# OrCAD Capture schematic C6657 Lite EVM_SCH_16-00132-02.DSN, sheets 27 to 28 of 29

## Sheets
27 PAGE26 : SMART REF & CORE VOLT: size C; title: UCD9222RGZR
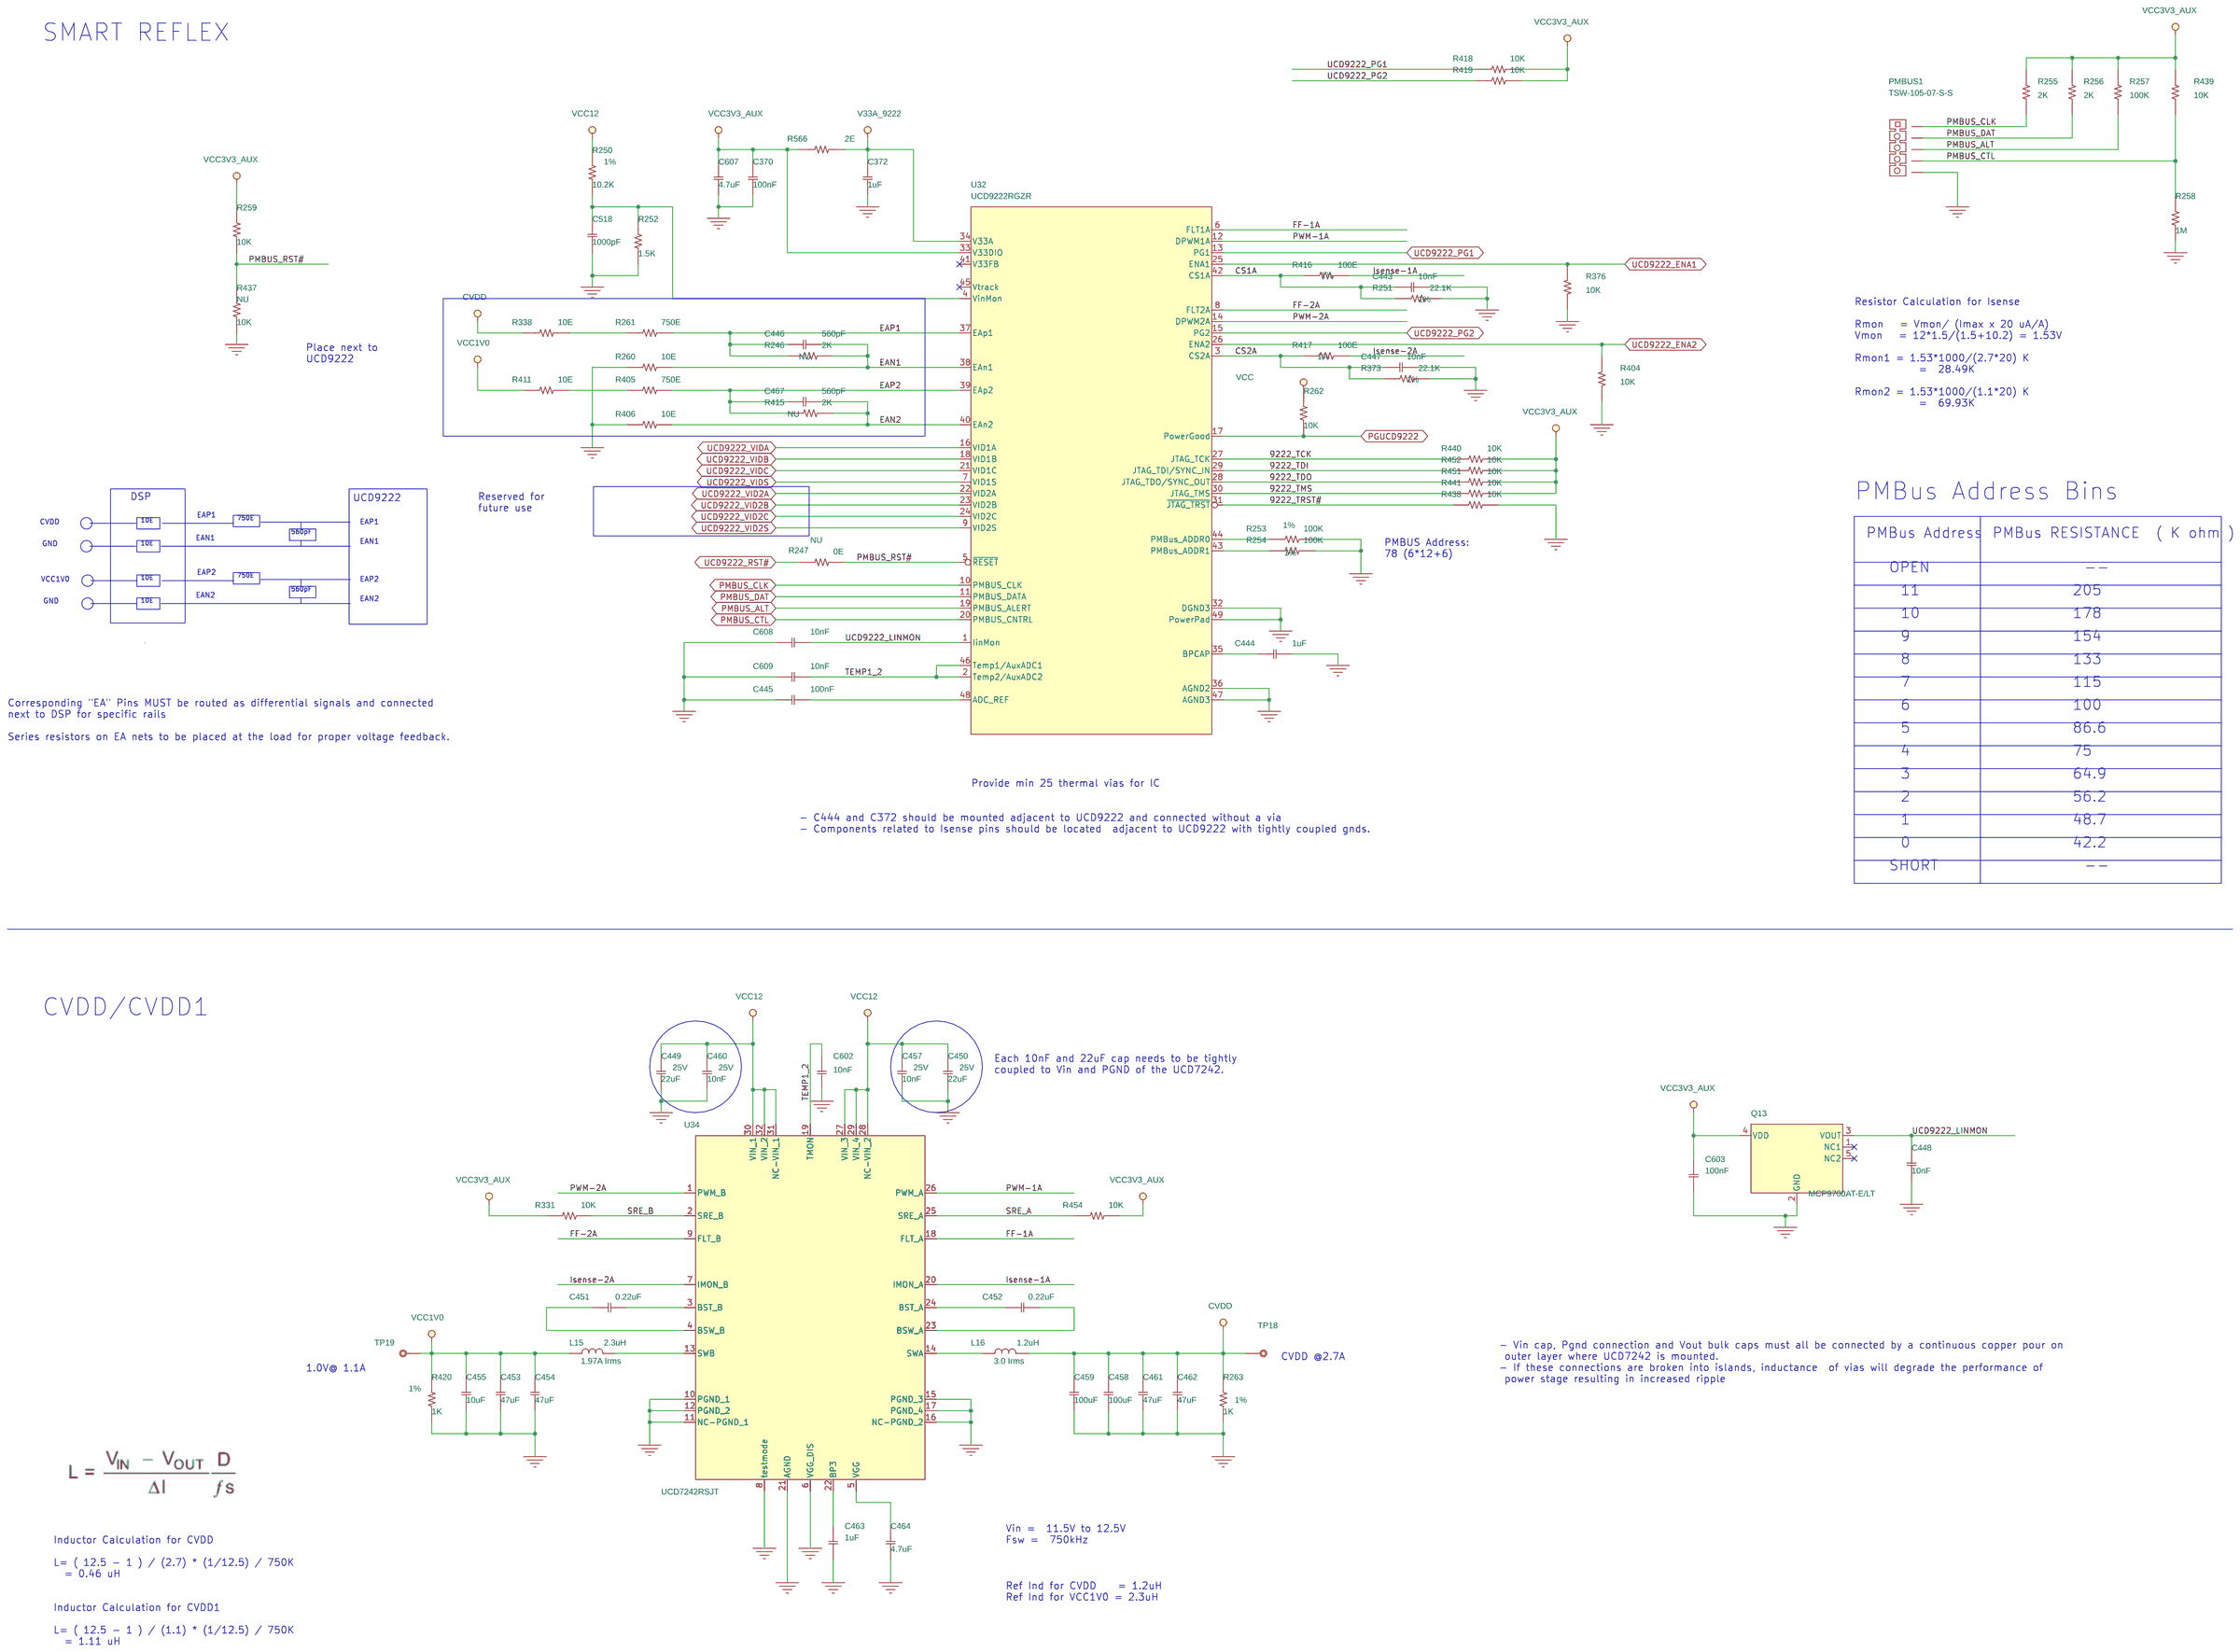
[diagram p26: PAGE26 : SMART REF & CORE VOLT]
28 PAGE18 : DSP-CLOCK & SMART REF: size C; title: DSP-CLOCK & SMART REFLEX
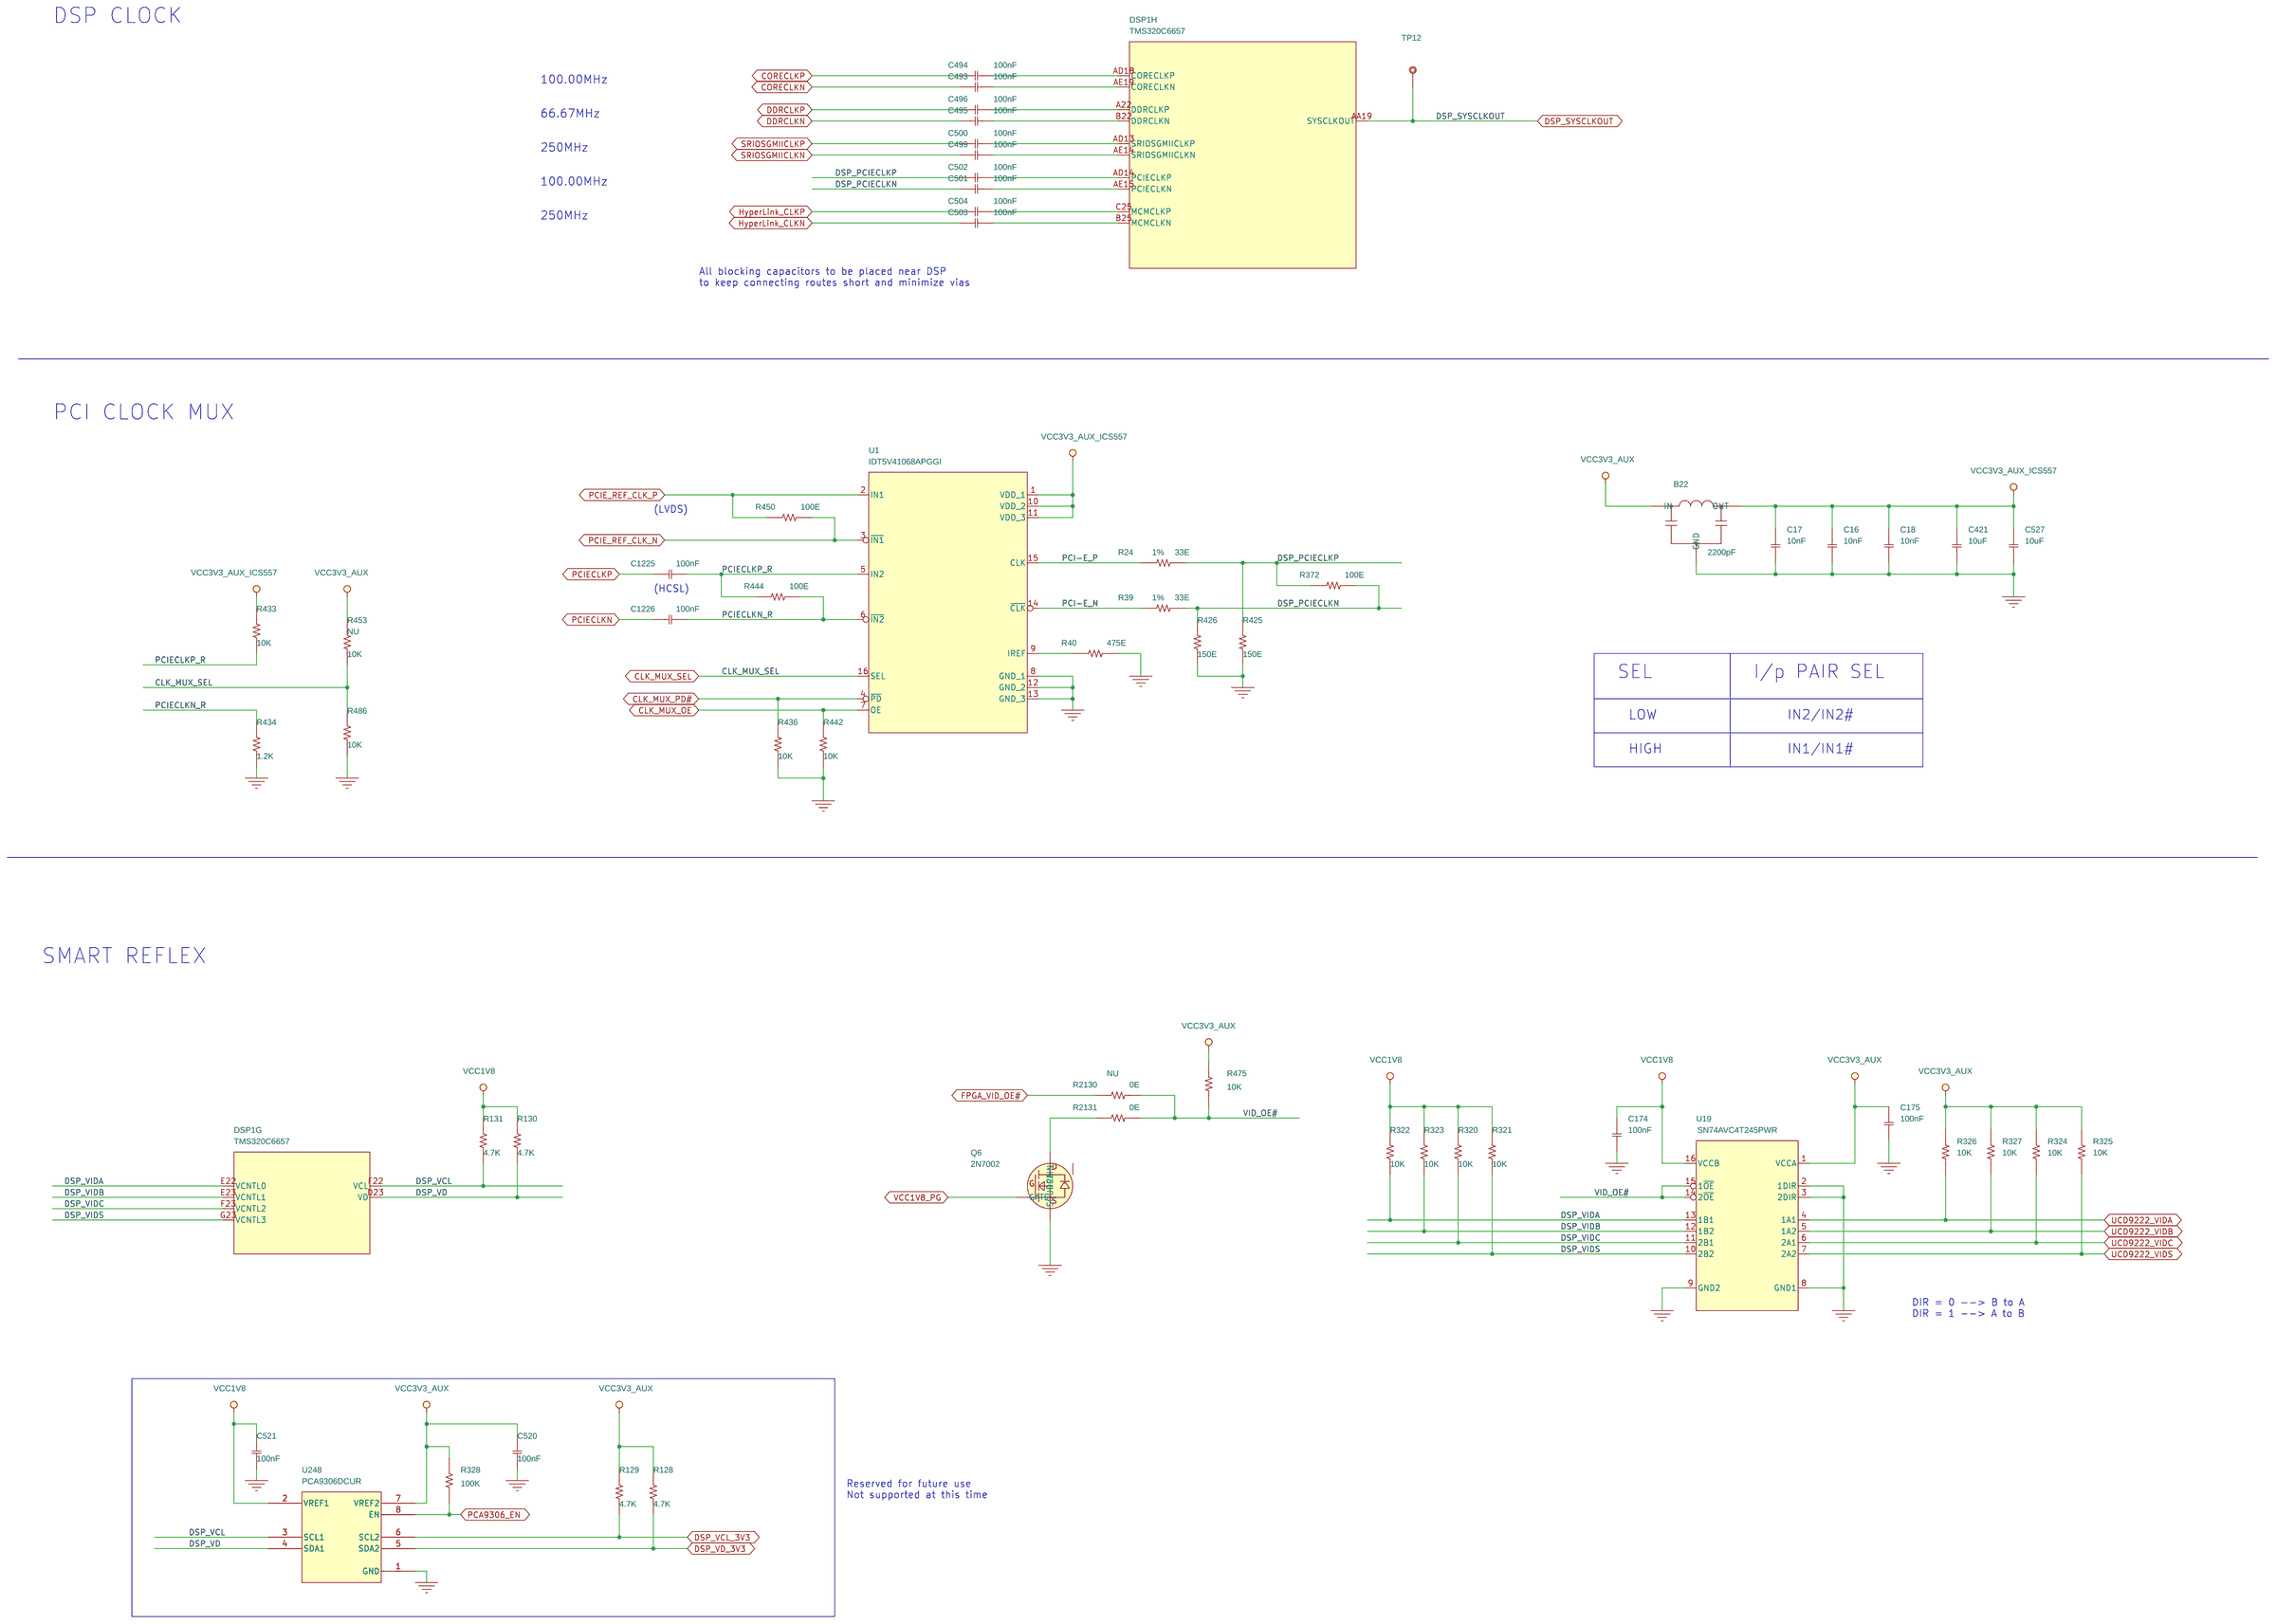
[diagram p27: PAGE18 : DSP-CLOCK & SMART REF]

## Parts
sheet PAGE18 : DSP-CLOCK & SMART REF
B22  2200pF  [L_3P_70_63X35]
C16  10nF  [C0402]
C17  10nF  [C0402]
C18  10nF  [C0402]
C174  100nF  [C0402]
C175  100nF  [C0402]
C421  10uF  [C0603]
C493  100nF  [C0402]
C494  100nF  [C0402]
C495  100nF  [C0402]
C496  100nF  [C0402]
C499  100nF  [C0402]
C500  100nF  [C0402]
C501  100nF  [C0402]
C502  100nF  [C0402]
C503  100nF  [C0402]
C504  100nF  [C0402]
C520  100nF  [C0402]
C521  100nF  [C0402]
C527  10uF  [C0603]
C1225  100nF  [C0402]
C1226  100nF  [C0402]
Q6  2N7002  [SOT-23]
R24  33E  [R0402]
R39  33E  [R0402]
R40  475E  [R0402]
R128  4.7K  [R0402]
R129  4.7K  [R0402]
R130  4.7K  [R0402]
R131  4.7K  [R0402]
R320  10K  [R0402]
R321  10K  [R0402]
R322  10K  [R0402]
R323  10K  [R0402]
R324  10K  [R0402]
R325  10K  [R0402]
R326  10K  [R0402]
R327  10K  [R0402]
R328  100K  [R0402]
R372  100E  [R0402]
R425  150E  [R0402]
R426  150E  [R0402]
R433  10K  [R0402]
R434  1.2K  [R0402]
R436  10K  [R0402]
R442  10K  [R0402]
R444  100E  [R0402]
R450  100E  [R0402]
R453  10K  [R0402]
R475  10K  [R0402]
R486  10K  [R0402]
R2130  0E  [R0402]
R2131  0E  [R0402]
TP12  Test Point  [TP-S40]
U1  IDT5V41068APGGI  [SOIC_16P_26_197x252]
U19  SN74AVC4T245PWR  [SOIC_16P_26_197x252]
U248  PCA9306DCUR  [SOIC_8P_20_79X122]
sheet PAGE25 : DSP_POWER 2
DSP1  TMS320C6657  [BGA80P_38X38_625_SKT_EINF]  (sections A,B,C,D,E,F,G,H,I,J,K,L,M,N,O,P,Q,R,S,T)
sheet PAGE26 : SMART REF & CORE VOLT
C370  100nF  [C0402]
C372  1uF  [C0402]
C443  10nF  [C0402]
C444  1uF  [C0402]
C445  100nF  [C0402]
C446  560pF  [C0402]
C447  10nF  [C0402]
C448  10nF  [C0402]
C449  22uF  [C1206-1]
C450  22uF  [C1206-1]
C451  0.22uF  [C0603]
C452  0.22uF  [C0603]
C453  47uF  [C0805]
C454  47uF  [C0805]
C455  10uF  [C0603]
C457  10nF  [C0402]
C458  100uF  [C1206-1]
C459  100uF  [C1206-1]
C460  10nF  [C0402]
C461  47uF  [C0805]
C462  47uF  [C0805]
C463  1uF  [C0402]
C464  4.7uF  [C0603]
C467  560pF  [C0402]
C518  1000pF  [C0402]
C602  10nF  [C0402]
C603  100nF  [C0402]
C607  4.7uF  [C0603]
C608  10nF  [C0402]
C609  10nF  [C0402]
L15  2.3uH  [IND_NRG4026]
L16  1.2uH  [CHK_ELL-5PRR47N]
PMBUS1  TSW-105-07-S-S  [HD_5x1P_100_D]
Q13  MCP9700AT-E/LT  [SC-70_5P]
R246  2K  [R0402]
R247  0E  [R0402]
R250  10.2K  [R0603]
R251  22.1K  [R0603]
R252  1.5K  [R0603]
R253  100K  [R0402]
R254  100K  [R0402]
R255  2K  [R0402]
R256  2K  [R0402]
R257  100K  [R0402]
R258  1M  [R0402]
R259  10K  [R0402]
R260  10E  [R0402]
R261  750E  [R0402]
R262  10K  [R0402]
R263  1K  [R0402]
R331  10K  [R0402]
R338  10E  [R0402]
R373  22.1K  [R0603]
R376  10K  [R0402]
R404  10K  [R0402]
R405  750E  [R0402]
R406  10E  [R0402]
R411  10E  [R0402]
R415  2K  [R0402]
R416  100E  [R0402]
R417  100E  [R0402]
R418  10K  [R0402]
R419  10K  [R0402]
R420  1K  [R0402]
R437  10K  [R0402]
R438  10K  [R0402]
R439  10K  [R0402]
R440  10K  [R0402]
R441  10K  [R0402]
R451  10K  [R0402]
R452  10K  [R0402]
R454  10K  [R0402]
R566  2E  [R0402]
TP18  Test Point  [TP-S40]
TP19  Test Point  [TP-S40]
U32  UCD9222RGZR  [QFN_48P_20_276x276_TP202V25]
U34  UCD7242RSJT  [QFN_32P_20_236x236_UDC7242]

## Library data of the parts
B22 = 1212_FILTER_NFW31SP106X1E4L_0: FILTER LC HIGH FREQ 2200PF 0603; Manufacture Part Number: NFM18CC222R1C3D; Mfg: Murata; Mfg Part#: NFM18CC222R1C3D; Oper. Temp. Range: -55C to 125C; Package: 0603; ProcessType: SMT; RoHS: Yes; Tolerance: 20%; Vendor: DigiKey; Vendor Part#: NFM18CC222R1C3D-ND; eI Part#: 04_00026_01
C16-C18 C443 C447 C448 C602 C608 C609 = 11_C_0: CAP 10nF 16V CERAMIC 0402 SMD; Alt Mfg: Murata; Alt Mfg Part#: GRM155R71C103KA01D; Manufacture Part Number: C1005X7R1C103K||2238 787 15636||CC0402KRX7R7BB103; Mfg: Panasonic - ECG; Mfg Part#: ECJ-0EB1C103K; Oper. Temp. Range: -55C to 125C; Package: 0402; ProcessType: SMT; RoHS: Yes; Tolerance: 10%; Vendor: DigiKey; Vendor Part#: PCC103BQCT-ND; eI Part#: 03_00025_01
C174 C175 C370 C445 C495 C496 C499-C504 C520 C521 C603 C1225 C1226 = 11_C_0: CAP CER 0.1UF 10V 10% X5R 0402; Alt Mfg: Murata; Alt Mfg Part#: GRM155R61A104KA01D; Manufacture Part Number: 2238 787 15649||CC0402KRX7R7BB104; Mfg: Yageo; Mfg Part#: CC0402KRX5R6BB104; Oper. Temp. Range: -55C to 85C; Package: 0402; ProcessType: SMT; RoHS: Yes; Tolerance: 10%; Vendor: DigiKey; Vendor Part#: 311-1336-1-ND; eI Part#: 03_00021_02
C421 C455 C527 = 11_C_0: CAP CER 10UF 6.3V 20% X5R 0603; Manufacture Part Number: C1608X5R0J106MT||2255 206 13776||CC0603MRX5R5BB106; Mfg: Murata; Mfg Part#: GRM188R60J106ME47D; Oper. Temp. Range: -55C to 85C; Package: 0603; ProcessType: SMT; RoHS: Yes; Tolerance: 20%; Vendor: DigiKey; Vendor Part#: 490-3896-1-ND; eI Part#: 03_00058_03
C493 C494 = 11_C_0: CAP CER 0.1UF 10V 10% X5R 0402; Alt Mfg: Murata; Alt Mfg Part#: GRM155R61A104KA01D; Manufacture Part Number: CC0402KRX7R7BB104; Mfg: Yageo; Mfg Part#: CC0402KRX5R6BB104; Oper. Temp. Range: -55C to 85C; Package: 0402; ProcessType: SMT; RoHS: Yes; Tolerance: 10%; Vendor: DigiKey; Vendor Part#: 311-1336-1-ND; eI Part#: 03_00021_02
Q6 = 131_N_MOS_SOT-23_1: MOSFET N-CH 60V 300MA SOT-23; Mfg: NXP Semiconductors; Mfg Part#: 2N7002,215; ProcessType: SMT; RoHS: Yes; Vendor: DigiKey; Vendor Part#: 568-1369-2-ND; eI Part#: 07_00015_02
R24 R39 = 10_R_0: RES 33.0 OHM 1/10W 1% 0402 SMD; Alt Mfg: Yageo; Alt Mfg Part#: RC0402FR-0733RL; Manufacture Part Number: 0402WGJ0330TCE||232270570339L||RC0402JR-0733RL||RM04JTN330; Mfg: Panasonic - ECG; Mfg Part#: ERJ-2RKF33R0X; Oper. Temp. Range: -55C to 125C; Package: 0402; ProcessType: SMT; Remark: Alt part is 1/16W; RoHS: Yes; Tolerance: 1%; Vendor: DigiKey; Vendor Part#: P33.0LCT-ND; eI Part#: 02_00018_05
R40 = 10_R_0: RES 475 OHM 1/10W 1% 0402 SMD; Manufacture Part Number: 0402WGF4750T5E||RM04FTN4750; Mfg: Panasonic - ECG; Mfg Part#: ERJ-2RKF4750X; Oper. Temp. Range: -55C to 125C; Package: 0402; ProcessType: SMT; Remark: Alt part is 1/16W; RoHS: Yes; Tolerance: 1%; Vendor: DigiKey; Vendor Part#: P475LCT-ND; eI Part#: 02_00690_01
R128-R131 = 10_R_0: RES 4.7K OHM 1/10W 5% 0402 SMD; Alt Mfg: Yageo; Alt Mfg Part#: RC0402JR-074K7L; Manufacture Part Number: 0402WGJ0472TCE||RC0402JR-074K7L||RM04JTN472; Mfg: Panasonic - ECG; Mfg Part#: ERJ-2GEJ472X; Oper. Temp. Range: -55C to 125C; Package: 0402; ProcessType: SMT; Remark: Alt part is 1/16W; RoHS: Yes; Tolerance: 5%; Vendor: DigiKey; Vendor Part#: P4.7KJCT-ND; eI Part#: 02_00023_01
R259 R262 R320-R327 R331 R376 R404 R418 R419 R436 R438-R442 R451 R452 R454 R475 R486 = 10_R_0: RES 10.0K OHM 1/10W 1% 0402 SMD; Alt Mfg: Yageo; Alt Mfg Part#: RC0402FR-0710KL; Manufacture Part Number: 0402WGF1002TCE||RM04FTN1002; Mfg: Panasonic - ECG; Mfg Part#: ERJ-2RKF1002X; Oper. Temp. Range: -55C ~ 125C; Package: 0402; ProcessType: SMT; Remark: Alt part is 1/16W; RoHS: Yes; Tolerance: 1%; Vendor: DigiKey; Vendor Part#: P10.0KLCT-ND; eI Part#: 02_00027_01
R328 = 10_R_0: RES 100K OHM 1/10W 1% 0402 SMD; Alt Mfg: Yageo; Alt Mfg Part#: RC0402FR-07100KL; Mfg: Panasonic - ECG; Mfg Part#: ERJ-2RKF1003X; Oper. Temp. Range: ±100ppm/°C; Package: 0402; ProcessType: SMT; RoHS: Yes; Tolerance: 1%; Vendor: DigiKey; Vendor Part#: P100KLCT-ND; eI Part#: 02_00262_01
R372 R444 R450 = 10_R_0: RES 100 OHM 1/10W 1% 0402 SMD; Manufacture Part Number: 0402WGJ0101TCE||RM04JTN101; Mfg: Panasonic - ECG; Mfg Part#: ERJ-2RKF1000X; Oper. Temp. Range: -55C to 125C; Package: 0402; ProcessType: SMT; RoHS: Yes; Tolerance: 1%; Vendor: DigiKey; Vendor Part#: P100LCT-ND; eI Part#: 02_00043_02
R425 R426 = 10_R_0: RES 150 OHM 1/10W 1% 0402 SMD; Manufacture Part Number: 0402WGF1500TCE||RM04FTN1500; Mfg: Panasonic - ECG; Mfg Part#: ERJ-2RKF1500X; Oper. Temp. Range: -55C to 125C; Package: 0402; ProcessType: SMT; RoHS: Yes; Tolerance: 1%; Vendor: DigiKey; Vendor Part#: P150LCT-ND; eI Part#: 02_00449_01
R433 = 10_R_0: RES 10.0K OHM 1/10W 1% 0402 SMD; Alt Mfg: Yageo; Alt Mfg Part#: RC0402FR-0710KL; Manufacture Part Number: 0402WGF1002TCE||RM04FTN1002; Mfg: Panasonic - ECG; Mfg Part#: ERJ-2RKF1002X; Oper. Temp. Range: -55C to 125C; Package: 0402; ProcessType: SMT; Remark: Alt part is 1/16W; RoHS: Yes; Tolerance: 1%; Vendor: DigiKey; Vendor Part#: P10.0KLCT-ND; eI Part#: 02_00027_01
R434 = 10_R_0: RES 1.20K OHM 1/10W 1% 0402 SMD; Alt Mfg: Yageo; Alt Mfg Part#: RC0402FR-071K2L; Mfg: Panasonic - ECG; Mfg Part#: ERJ-2RKF1201X; Oper. Temp. Range: -55C to 125C; Package: 0402; ProcessType: SMT; RoHS: Yes; Tolerance: 1%; Vendor: DigiKey; Vendor Part#: P1.20KLCT-ND; eI Part#: 02_00143_03
R437 R453 = 10_R_0: RES 10.0K OHM 1/10W 1% 0402 SMD; Alt Mfg: Yageo; Alt Mfg Part#: RC0402FR-0710KL; Manufacture Part Number: 0402WGF1002TCE||RM04FTN1002; Mfg: Panasonic - ECG; Mfg Part#: ERJ-2RKF1002X; Mounting Status: NU; Mounting_Status: NU; Oper. Temp. Range: -55C ~ 125C; Package: 0402; ProcessType: SMT; Remark: Alt part is 1/16W; RoHS: Yes; Tolerance: 1%; Vendor: DigiKey; Vendor Part#: P10.0KLCT-ND; eI Part#: 02_00027_01
R247 R2130 = 10_R_0: RES ZERO OHM 1/10W 5% 0402 SMD; Alt Mfg: Yageo; Alt Mfg Part#: RC0402JR-070RL; Mfg: Panasonic - ECG; Mfg Part#: ERJ-2GE0R00X; Mounting Status: NU; Mounting_Status: NU; Oper. Temp. Range: -55C to 125C; Package: 0402; ProcessType: SMT; Remark: Alt part is 1/16W; RoHS: Yes; Tolerance: 5%; Vendor: DigiKey; Vendor Part#: P0.0JCT-ND; eI Part#: 02_00019_01
R2131 = 10_R_0: RES ZERO OHM 1/10W 5% 0402 SMD; Alt Mfg: Yageo; Alt Mfg Part#: RC0402JR-070RL; Mfg: Panasonic - ECG; Mfg Part#: ERJ-2GE0R00X; Oper. Temp. Range: -55C to 125C; Package: 0402; ProcessType: SMT; Remark: Alt part is 1/16W; RoHS: Yes; Tolerance: 5%; Vendor: DigiKey; Vendor Part#: P0.0JCT-ND; eI Part#: 02_00019_01
TP12 TP18 TP19 = 00_TP-S40_0: TEST PAD TP-S40; Mfg: --NA--; Mfg Part#: --NA--; Oper. Temp. Range: --NA--; Package: --NA--; ProcessType: SMT; RoHS: Yes; Vendor: --NA--; Vendor Part#: --NA--; eI Part#: --NA--
U1 = ICS557GI-08LFT_0: IC CLK MUX 2:1 16TSSOP; Mfg: IDT, Integrated Device Technology Inc; Oper. Temp. Range: -40°C ~ 85°C; Package: 16-TSSOP; RoHS: Yes; Specifications: IC CLK MUX 2:1 16TSSOP; Vendor: DigiKey; Vendor Part#: 800-2530-5-ND; eI Part#: 01_00854_01
U19 = SN74AVC4T245PWR: IC BUS TRANSCVR 4BIT 16TSSOP; Mfg: Texas Instruments; Oper. Temp. Range: -40°C ~ 85°C; Package: 16-TSSOP; RoHS: Yes; Specifications: IC BUS TRANSCVR 4BIT 16TSSOP; Vendor: Texas Instruments; eI Part#: 01_00045_01
U248 = PCA9306: IC, Dual I2C Voltage Translator; Alt Mfg: NXP Semiconductors; Alt Mfg Part#: PCA9306DC1,125; Mfg: Texas Instruments; Oper. Temp. Range: -40C to 85C; Package: 8-VSSOP; RoHS: Yes; Specifications: IC, Dual I2C Voltage Translator; Vendor: Digikey; Vendor Part#: 296-17988-1-ND; eI Part#: 01_00044_01
DSP1 = TMS320C6657: TI DSP, Dual C66x™ DSP Cores; Mfg: Texas Instruments; RoHS: Yes; Vendor: Texas Instruments; eI Part#: 01_00878_01
C372 C444 C463 = 11_C_0: CAP CER 1.0UF 16V X5R 0402; Manufacture Part Number: C1005X5R0J105KT||C0402B105K007T; Mfg: TDK Corp; Mfg Part#: C1005X5R1C105K; Oper. Temp. Range: -55C to 85C; Package: 0402; ProcessType: SMT; RoHS: Yes; Tolerance: 10%; Vendor: DigiKey; Vendor Part#: 445-4978-1-ND; eI Part#: 03_00264_01
C446 C467 = 11_C_0: CAP CER 560PF 50V 10% X7R 0402; Alt Mfg: AVX; Alt Mfg Part#: 04025C561KAT2A; Manufacture Part Number: 223858715619; Mfg: Yageo; Mfg Part#: CC0402KRX7R9BB561; Oper. Temp. Range: -55C to 125C; Package: 0402; ProcessType: SMT; RoHS: Yes; Tolerance: 10%; Vendor: DigiKey; Vendor Part#: 311-1029-1-ND; eI Part#: 03_00108_05
C449 C450 = 11_C_0: CAP CER 22UF 25V 10% X5R 1206; Manufacture Part Number: KC30R1C226M-T; Mfg: Murata; Mfg Part#: GRM31CR61E226KE15L; Oper. Temp. Range: -55C to 85C; Package: 1206; ProcessType: SMT; RoHS: Yes; Tolerance: 10%; Vendor: DigiKey; Vendor Part#: 490-5527-1-ND; Voltage: 25V; eI Part#: 03_00442_01
C451 C452 = 11_C_0: CAP CER 0.22UF 25V 10% X7R 0603; Manufacture Part Number: C0603X224K025T; Mfg: Murata; Mfg Part#: GRM188R71E224KA88D; Oper. Temp. Range: -55C ~ 125C; Package: 0603; ProcessType: SMT; RoHS: Yes; Tolerance: 10%; Vendor: DigiKey; Vendor Part#: 490-3290-1-ND; eI Part#: 03_00115_01
C453 C454 C461 C462 = 11_C_0: CAP CER 47UF 6.3V 20% X5R 0805; Mfg: Taiyo Yuden; Mfg Part#: JMK212BJ476MG-T; Oper. Temp. Range: -55C to 105C; Package: 0805; ProcessType: SMT; RoHS: Yes; Tolerance: 20%; Vendor: DigiKey; Vendor Part#: 587-1779-1-ND; eI Part#: 03_00328_01
C457 C460 = 11_C_0: CAP CER 10000PF 25V 10% X7R 0402; Mfg: Yageo; Mfg Part#: CC0402KRX7R8BB103; Oper. Temp. Range: -55C to 125C; Package: 0402; ProcessType: SMT; RoHS: Yes; Tolerance: 10%; Vendor: DigiKey; Vendor Part#: 311-1337-1-ND; Voltage: 25V; eI Part#: 03_00029_07
C458 C459 = 11_C_0: CAP CER 100UF 6.3V 20% X5R 1206; Manufacture Part Number: JMK316BJ107ML-T; Mfg: Taiyo Yuden; Mfg Part#: JMK316BJ107ML-T; Oper. Temp. Range: -55C to 85C; Package: 1206; ProcessType: SMT; RoHS: Yes; Tolerance: 20%; Vendor: DigiKey; Vendor Part#: 587-1963-1-ND; Voltage: 6.3V; eI Part#: 03_00380_04
C464 C607 = 11_C_0: CAP CER 4.7UF 10V Y5V 0603; Manufacture Part Number: GRM188R60J475K||C1608X5R0J475KT; Mfg: Murata; Mfg Part#: GRM188F51A475ZE20D; Oper. Temp. Range: -55C to 85C; Package: 0603; ProcessType: SMT; RoHS: Yes; Tolerance: 10%; Vendor: DigiKey; Vendor Part#: 490-3302-1-ND; eI Part#: 03_00276_01
C518 = 11_C_0: CAP CER 1000PF 25V X7R 0402; Manufacture Part Number: 223858715623||CC0402KRX7R9BB102; Mfg: Johnson Dielectrics Inc; Mfg Part#: 250R07W102KV4T; Oper. Temp. Range: -55C to 125C; Package: 0402; ProcessType: SMT; RoHS: Yes; Tolerance: 10%; Vendor: DigiKey; Vendor Part#: 709-1131-1-ND; eI Part#: 03_00289_01
L15 = 1211_CHOKE_0: INDUCTOR 2.3UH 1.97A 30% SMD; Current: 1.97A Irms; Mfg: Taiyo Yuden; Mfg Part#: NRG4026T2R3N; Oper. Temp. Range: -55C ~ 125C; Package: 4.00mm x 4.00mm x 2.60mm; ProcessType: SMT; RoHS: Yes; Tolerance: 30%; Vendor: DigiKey; Vendor Part#: 587-2379-1-ND; eI Part#: 04_00282_01
L16 = 1211_CHOKE_0: COIL CHOKE 1.2UH SHIELDED SMD; Current: 3.0 Irms; Mfg: Panasonic - ECG; Mfg Part#: ELL-5PR1R2N; Oper. Temp. Range: -55C ~ 125C; Package: 5.00mm x 5.00mm x 1.85mm; ProcessType: SMT; RoHS: Yes; Tolerance: 30%; Vendor: DigiKey; Vendor Part#: PCD2372CT-ND; eI Part#: 04_00283_01
PMBUS1 = 1653_JH5X1V_0: CONN HEADER 5POS .100" SGL GOLD; Manufacture Part Number: 205-15GS SERIES||1130-000-05S||21N12564-05S10B-01G-6/3; Mfg: Samtec; Package: PH5x1P-2.54; ProcessType: DIP; RoHS: Yes; Vendor: DigiKey; Vendor Part#: SAM1033-05-ND; eI Part#: 09_00658_01
Q13 = 141_MICROCHIP_MCP9700AT-E-LT_0: IC SENSOR THERMAL 2.3V SC70-5; Mfg: Microchip Technology; Oper. Temp. Range: -40°C ~ 125°C; Package: SC70-5; ProcessType: SMT; RoHS: Yes; Vendor: DigiKey; Vendor Part#: MCP9700AT-E/LTCT-ND; eI Part#: 01_00850_01
R246 R415 = 10_R_0: RES 2.00K OHM 1/10W 1% 0402 SMD; Alt Mfg: TE Connectivity; Alt Mfg Part#: 5-1879208-6; Manufacture Part Number: 0402WGF2001TCE||RM04FTN2001; Mfg: Panasonic - ECG; Mfg Part#: ERJ-2RKF2001X; Mounting Status: NU; Mounting_Status: NU; Oper. Temp. Range: -55C to 125C; Package: 0402; ProcessType: SMT; Remark: Alt part is 1/16W; RoHS: Yes; Tolerance: 1%; Vendor: DigiKey; Vendor Part#: P2.00KLCT-ND; eI Part#: 02_00229_02
R250 = 10_R_0: RES 10.2K OHM 1/10W 1% 0603 SMD; Manufacture Part Number: 0603WAF1022T5E||232270461023L||RM06FTN1022; Mfg: Panasonic - ECG; Mfg Part#: ERJ-3EKF1022V; Oper. Temp. Range: -55C to 125C; Package: 0603; ProcessType: SMT; RoHS: Yes; Tolerance: 1%; Vendor: DigiKey; Vendor Part#: P10.2KHCT-ND; eI Part#: 02_00739_01
R251 R373 = 10_R_0: RES 22.1K OHM 1/10W 1% 0603 SMD; Mfg: Yageo; Mfg Part#: RC0603FR-0722K1L; Oper. Temp. Range: -55C to 125C; Package: 0603; ProcessType: SMT; RoHS: Yes; Tolerance: 1%; Vendor: DigiKey; Vendor Part#: 311-22.1KHRCT-ND; eI Part#: 02_00491_02
R252 = 10_R_0: RES 1.50K OHM 1/10W 1% 0603 SMD; Manufacture Part Number: 0603WAF1501T5E||232270461502L||RM06FTN1501; Mfg: Panasonic - ECG; Mfg Part#: ERJ-3EKF1501V; Oper. Temp. Range: -55C to 125C; Package: 0603; ProcessType: SMT; RoHS: Yes; Tolerance: 1%; Vendor: DigiKey; Vendor Part#: P1.50KHCT-ND; eI Part#: 02_00122_02
R253 R254 R257 = 10_R_0: RES 100K OHM 1/10W 1% 0402 SMD; Alt Mfg: Yageo; Alt Mfg Part#: RC0402FR-07100KL; Manufacture Part Number: 0402WGF1003TCE||RM04FTN1003; Mfg: Panasonic - ECG; Mfg Part#: ERJ-2RKF1003X; Oper. Temp. Range: ±100ppm/°C; Package: 0402; ProcessType: SMT; RoHS: Yes; Tolerance: 1%; Vendor: DigiKey; Vendor Part#: P100KLCT-ND; eI Part#: 02_00262_01
R255 R256 = 10_R_0: RES 2.00K OHM 1/10W 1% 0402 SMD; Alt Mfg: TE Connectivity; Alt Mfg Part#: 5-1879208-6; Manufacture Part Number: 0402WGF2001TCE||RM04FTN2001; Mfg: Panasonic - ECG; Mfg Part#: ERJ-2RKF2001X; Oper. Temp. Range: -55C to 125C; Package: 0402; ProcessType: SMT; Remark: Alt part is 1/16W; RoHS: Yes; Tolerance: 1%; Vendor: DigiKey; Vendor Part#: P2.00KLCT-ND; eI Part#: 02_00229_02
R258 = 10_R_0: RES 1.00M OHM 1/16W 1% 0402 SMD; Manufacture Part Number: 0402WGF4991TCE||RM04FTN4991; Mfg: Yageo; Mfg Part#: RC0402FR-071ML; Mounting Status: NU; Mounting_Status: NU; Oper. Temp. Range: -55C to 125C; Package: 0402; ProcessType: SMT; Remark: Alt part is 1/16W; RoHS: Yes; Tolerance: 1%; Vendor: DigiKey; Vendor Part#: 311-1.00MLRCT-ND; eI Part#: 02_00057_02
R260 R338 R406 R411 = 10_R_0: RES 10.0 OHM 1/10W 1% 0402 SMD; Manufacture Part Number: 0402WGJ0100TCE||RC0402JR-0710RL||RM04JTN100; Mfg: Panasonic - ECG; Mfg Part#: ERJ-2RKF10R0X; Oper. Temp. Range: -55C to 125C; Package: 0402; ProcessType: SMT; RoHS: Yes; Tolerance: 1%; Vendor: DigiKey; Vendor Part#: P10.0LCT-ND; eI Part#: 02_00060_01
R261 R405 = 10_R_0: RES 750 OHM 1/10W 1% 0402 SMD; Manufacture Part Number: 0402WGF7500T5E||0402WGF7500TCE||RM04FTN7500; Mfg: Panasonic - ECG; Mfg Part#: ERJ-2RKF7500X; Oper. Temp. Range: -55C to 125C; Package: 0402; ProcessType: SMT; RoHS: Yes; Tolerance: 1%; Vendor: DigiKey; Vendor Part#: P750LCT-ND; eI Part#: 02_00447_01
R263 R420 = 10_R_0: RES 1.00K OHM 1/10W 1% 0402 SMD; Alt Mfg: Yageo; Alt Mfg Part#: RC0402FR-071KL; Manufacture Part Number: 0402WGF1001TCE||RM04FTN1001; Mfg: Panasonic - ECG; Mfg Part#: ERJ-2RKF1001X; Oper. Temp. Range: -55C to 125C; Package: 0402; ProcessType: SMT; RoHS: Yes; Tolerance: 1%; Vendor: DigiKey; Vendor Part#: P1.00KLCT-ND; eI Part#: 02_00045_01
R416 R417 = 10_R_0: RES 100 OHM 1/10W 1% 0402 SMD; Manufacture Part Number: 0402WGF1000TCE||232270671001L||RM04FTN1000; Mfg: Panasonic - ECG; Mfg Part#: ERJ-2RKF1000X; Oper. Temp. Range: -55C to 125C; Package: 0402; ProcessType: SMT; RoHS: Yes; Tolerance: 1%; Vendor: DigiKey; Vendor Part#: P100LCT-ND; eI Part#: 02_00043_02
R566 = 10_R_0: RES 2.00 OHM 1/16W 1% 0402 SMD; Manufacture Part Number: 0603WAF1501T5E||232270461502L||RM06FTN1501; Mfg: Vishay/Dale; Mfg Part#: CRCW04022R00FKED; Oper. Temp. Range: -55C to 125C; Package: 0402; ProcessType: SMT; RoHS: Yes; Tolerance: 1%; Vendor: DigiKey; Vendor Part#: 541-2.00LLCT-ND; eI Part#: 02_00669_02
U32 = UCD9222RGZR: IC DGTL PWM SYST CTRLR 48VQFN; Mfg: Texas Instruments; Oper. Temp. Range: -40°C ~ 125°C; Package: 48-VFQFN; RoHS: Yes; Vendor: DigiKey; Vendor Part#: UCD9222RGZR-ND; eI Part#: 01_00842_01
U34 = 141_TI_UCD7242RSJT_0: IC BUCK SYNC 10A DL 32QFN; Mfg: Texas Instruments; Oper. Temp. Range: -40°C ~ 125°C; Package: QFN32; ProcessType: SMT; RoHS: Yes; Vendor: DigiKey; Vendor Part#: 296-27191-1-ND; eI Part#: 01_00843_01

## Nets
GND: B22.2(GND) C16.2 C17.2 C18.2 C174.1 C175.2 C370.2 C372.2 C421.2 C443.2 C444.1 C445.1 C447.2 C448.1 C449.1 C450.1 C453.2 C454.2 C455.2 C457.1 C458.2 C459.2 C460.1 C461.2 C462.2 C463.2 C464.2 C518.2 C520.2 C521.1 C527.2 C602.1 C603.2 C607.2 C608.1 C609.1 PMBUS1.5 Q6.2(SOURCE) Q13.2(GND) R40.2 R251.2 R252.2 R253.2 R254.2 R258.1 R260.1 R263.1 R373.2 R376.2 R404.2 R406.1 R420.1 R425.1 R426.1 R434.2 R436.2 R437.2 R438.2 R442.2 R486.2 U1.8(GND_1) U1.12(GND_2) U1.13(GND_3) U19.2(1DIR) U19.3(2DIR) U19.8(GND1) U19.9(GND2) U32.32(DGND3) U32.36(AGND2) U32.47(AGND3) U32.49(PowerPad) U34.6(VGG_DIS) U34.8(testmode) U34.10(PGND_1) U34.11(NC-PGND_1) U34.12(PGND_2) U34.15(PGND_3) U34.16(NC-PGND_2) U34.17(PGND_4) U34.21(AGND) U248.1(GND) ; also on sheet 4 5 6 7 8 9 12 13 14 15 16 19 20 23 26 29
V33A_9222: C372.1 R566.2 U32.34(V33A)
VCC1V0: C453.1 C454.1 C455.1 L15.1 R411.1 R420.2 TP19.1 ; also on sheet 7
VCC1V8: C174.2 C521.2 R130.2 R131.2 R320.1 R321.1 R322.1 R323.1 U19.16(VCCB) U248.2(VREF1) ; also on sheet 4 5 6 9 12 13 15 16
VCC1V8_PG: Q6.1(GATE) ; also on sheet 15 29
VCC3V3_AUX: B22.1(IN) C175.1 C370.1 C520.1 C603.1 C607.1 Q13.4(VDD) R128.2 R129.2 R255.2 R256.2 R257.2 R259.1 R262.1 R324.1 R325.1 R326.1 R327.1 R328.1 R331.2 R418.1 R419.1 R439.1 R440.1 R441.1 R451.1 R452.1 R453.2 R454.1 R475.1 R566.1 U19.1(VCCA) U32.33(V33DIO) U248.7(VREF2) ; also on sheet 4 6 12 13 14 15 16 20 23 26 29
VCC3V3_AUX_ICS557: B22.3(OUT) C16.1 C17.1 C18.1 C421.1 C527.1 R433.1 U1.1(VDD) U1.10(VDD_2) U1.11(VDD_3)
VCC12: C449.2 C450.2 C457.2 C460.2 R250.1 U34.27(VIN_3) U34.28(NC-VIN_2) U34.29(VIN_4) U34.30(VIN_1) U34.31(NC-VIN_1) U34.32(VIN_2) ; also on sheet 12 14
9222_TCK: R440.2 U32.27(JTAG_TCK)
9222_TDI: R452.2 U32.29(JTAG_TDI/SYNC_IN)
9222_TDO: R451.2 U32.28(JTAG_TDO/SYNC_OUT)
9222_TMS: R441.2 U32.30(JTAG_TMS)
9222_TRST#: R438.1 U32.31(~{JTAG_TRST})
CLK_MUX_OE: R442.1 U1.7(OE) ; also on sheet 29
CLK_MUX_PD#: R436.1 U1.4(~{PD}) ; also on sheet 29
CLK_MUX_SEL: R453.1 R486.1 U1.16(SEL) ; also on sheet 29
CORECLKN: C493.1 ; also on sheet 20
CORECLKP: C494.1 ; also on sheet 20
CS1A: C443.1 R251.1 R416.1 U32.42(CS1A)
CS2A: C447.1 R373.1 R417.1 U32.3(CS2A)
CVDD: C458.1 C459.1 C461.1 C462.1 L16.2 R263.2 R338.1 TP18.1 ; also on sheet 9
DDRCLKN: C495.1 ; also on sheet 20
DDRCLKP: C496.1 ; also on sheet 20
DSP_PCIECLKN: C501.1 R39.2 R372.2 R426.2
DSP_PCIECLKP: C502.1 R24.2 R372.1 R425.2
DSP_SYSCLKOUT: DSP1.AA19(SYSCLKOUT) TP12.1 ; also on sheet 29
DSP_VCL: DSP1.F22(VCL) R131.1 U248.3(SCL1)
DSP_VCL_3V3: R129.1 U248.6(SCL2) ; also on sheet 29
DSP_VD: DSP1.D23(VD) R130.1 U248.4(SDA1)
DSP_VD_3V3: R128.1 U248.5(SDA2) ; also on sheet 29
DSP_VIDA: DSP1.E22(VCNTL0) R322.2 U19.13(1B1)
DSP_VIDB: DSP1.E23(VCNTL1) R323.2 U19.12(1B2)
DSP_VIDC: DSP1.F23(VCNTL2) R320.2 U19.11(2B1)
DSP_VIDS: DSP1.G23(VCNTL3) R321.2 U19.10(2B2)
EAN1: C446.2 R246.2 R260.2 U32.38(EAn1)
EAN2: C467.2 R406.2 R415.2 U32.40(EAn2)
EAP1: C446.1 R246.1 R261.2 U32.37(EAp1)
EAP2: C467.1 R405.2 R415.1 U32.39(EAp2)
FF-1A: U32.6(FLT1A) U34.18(FLT_A)
FF-2A: U32.8(FLT2A) U34.9(FLT_B)
FPGA_VID_OE#: R2130.1 ; also on sheet 26
HyperLink_CLKN: C503.1 ; also on sheet 20
HyperLink_CLKP: C504.1 ; also on sheet 20
Isense-1A: R416.2 U34.20(IMON_A)
Isense-2A: R417.2 U34.7(IMON_B)
PCA9306_EN: R328.2 U248.8(EN) ; also on sheet 29
PCI-E_N: R39.1 U1.14(~{CLK})
PCI-E_P: R24.1 U1.15(CLK)
PCIE_REF_CLK_N: R450.2 U1.3(~{IN1}) ; also on sheet 12
PCIE_REF_CLK_P: R450.1 U1.2(IN1) ; also on sheet 12
PCIECLKN: C1226.2 ; also on sheet 20
PCIECLKN_R: C1226.1 R434.1 R444.2 U1.6(~{IN2})
PCIECLKP: C1225.2 ; also on sheet 20
PCIECLKP_R: C1225.1 R433.2 R444.1 U1.5(IN2)
PGUCD9222: R262.2 U32.17(PowerGood) ; also on sheet 29
PMBUS_ALT: PMBUS1.3 R257.1 U32.19(PMBUS_ALERT) ; also on sheet 29
PMBUS_CLK: PMBUS1.1 R255.1 U32.10(PMBUS_CLK) ; also on sheet 29
PMBUS_CTL: PMBUS1.4 R258.2 R439.2 U32.20(PMBUS_CNTRL) ; also on sheet 29
PMBUS_DAT: PMBUS1.2 R256.1 U32.11(PMBUS_DATA) ; also on sheet 29
PMBUS_RST#: R247.2 R259.2 R437.1 U32.5(~{RESET})
PWM-1A: U32.12(DPWM1A) U34.26(PWM_A)
PWM-2A: U32.14(DPWM2A) U34.1(PWM_B)
SRE_A: R454.2 U34.25(SRE_A)
SRE_B: R331.1 U34.2(SRE_B)
SRIOSGMIICLKN: C499.1 ; also on sheet 20
SRIOSGMIICLKP: C500.1 ; also on sheet 20
TEMP1_2: C602.2 C609.2 U32.2(Temp2/AuxADC2) U32.46(Temp1/AuxADC1) U34.19(TMON)
UCD9222_ENA1: R376.1 U32.25(ENA1) ; also on sheet 29
UCD9222_ENA2: R404.1 U32.26(ENA2) ; also on sheet 29
UCD9222_LINMON: C448.2 C608.2 Q13.3(VOUT) U32.1(IinMon)
UCD9222_PG1: R418.2 U32.13(PG1) ; also on sheet 29
UCD9222_PG2: R419.2 U32.15(PG2) ; also on sheet 29
UCD9222_RST#: R247.1 ; also on sheet 29
UCD9222_VID2A: U32.22(VID2A) ; also on sheet 26
UCD9222_VID2B: U32.23(VID2B) ; also on sheet 26
UCD9222_VID2C: U32.24(VID2C) ; also on sheet 26
UCD9222_VID2S: U32.9(VID2S) ; also on sheet 26
UCD9222_VIDA: R326.2 U19.4(1A1) U32.16(VID1A)
UCD9222_VIDB: R327.2 U19.5(1A2) U32.18(VID1B)
UCD9222_VIDC: R324.2 U19.6(2A1) U32.21(VID1C)
UCD9222_VIDS: R325.2 U19.7(2A2) U32.7(VID1S)
VID_OE#: R475.2 R2130.2 R2131.2 U19.14(2~{OE}) U19.15(1~{OE})
N36485154: C445.2 U32.48(ADC_REF)
N36801889: L16.1 U34.14(SWA)
N36837047: C452.1 U34.24(BST_A)
N36837049: C452.2 U34.23(BSW_A)
N36891843: C463.1 U34.22(BP3)
N36895116: C464.1 U34.5(VGG)
N39983645: C494.2 DSP1.AD18(CORECLKP)
N39984987: C493.2 DSP1.AE19(CORECLKN)
N39986350: C495.2 DSP1.B22(DDRCLKN)
N39986372: C496.2 DSP1.A22(DDRCLKP)
N39989132: C499.2 DSP1.AE14(SRIOSGMIICLKN)
N39989154: C500.2 DSP1.AD13(SRIOSGMIICLKP)
N39990529: C501.2 DSP1.AE15(PCIECLKN)
N39990551: C502.2 DSP1.AD14(PCIECLKP)
N39991930: C503.2 DSP1.B25(MCMCLKN)
N39991952: C504.2 DSP1.C25(MCMCLKP)
N44390091: C451.2 U34.3(BST_B)
N44390118: C451.1 U34.4(BSW_B)
N44390236: L15.2 U34.13(SWB)
N61566795: R261.1 R338.2
N61573944: R405.1 R411.2
N70094016: R253.1 U32.44(PMBus_ADDR0)
N70094170: R254.1 U32.43(PMBus_ADDR1)
N70094774: C444.2 U32.35(BPCAP)
N70096049: C518.1 R250.2 R252.1 U32.4(VinMon)
N70219906: R40.1 U1.9(IREF)
N79304095: Q6.3(DRAIN) R2131.1

Not connected (* = marked no-connect by the designer): Q13 1(NC1)* 5(NC2)*; U32 41(V33FB)* 45(Vtrack)*

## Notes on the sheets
sheet 27
- SMART REFLEX
- Resistor Calculation for Isense
  Rmon   = Vmon/ (Imax x 20 uA/A)
  Vmon   = 12*1.5/(1.5+10.2) = 1.53V
  Rmon1 = 1.53*1000/(2.7*20) K
              =  28.49K
  Rmon2 = 1.53*1000/(1.1*20) K
              =  69.93K
- Place next to
  UCD9222
- DSP
- Reserved for
  future use
- PMBus Address Bins
- UCD9222
- CVDD
- 10E
- EAP1
- 750E
- EAP1
- 560pF
- PMBus Address
- PMBus RESISTANCE  ( K ohm )
- GND
- 10E
- EAN1
- EAN1
- PMBUS Address:
  78 (6*12+6)
- EAP2
- 750E
- OPEN
- --
- VCC1V0
- 10E
- 560pF
- EAP2
- 11
- 205
- GND
- 10E
- EAN2
- EAN2
- 10
- 178
- 9
- 154
- 8
- 133
- 7
- 115
- Corresponding "EA" Pins MUST be routed as differential signals and connected
  next to DSP for specific rails
  Series resistors on EA nets to be placed at the load for proper voltage feedback.
- 6
- 100
- 5
- 86.6
- 4
- 75
- 3
- 64.9
- Provide min 25 thermal vias for IC
- 2
- 56.2
- - C444 and C372 should be mounted adjacent to UCD9222 and connected without a via
  - Components related to Isense pins should be located  adjacent to UCD9222 with tightly coupled gnds.
- 1
- 48.7
- 0
- 42.2
- SHORT
- --
- CVDD/CVDD1
- Each 10nF and 22uF cap needs to be tightly
  coupled to Vin and PGND of the UCD7242.
- - Vin cap, Pgnd connection and Vout bulk caps must all be connected by a continuous copper pour on
   outer layer where UCD7242 is mounted.
  - If these connections are broken into islands, inductance  of vias will degrade the performance of
   power stage resulting in increased ripple
- CVDD @2.7A
- 1.0V@ 1.1A
- Vin =  11.5V to 12.5V
  Fsw =  750kHz
- Inductor Calculation for CVDD
  L= ( 12.5 - 1 ) / (2.7) * (1/12.5) / 750K
    = 0.46 uH
  Inductor Calculation for CVDD1
  L= ( 12.5 - 1 ) / (1.1) * (1/12.5) / 750K
    = 1.11 uH
- Ref Ind for CVDD    = 1.2uH
  Ref Ind for VCC1V0 = 2.3uH
sheet 28
- DSP CLOCK
- 100.00MHz
- 66.67MHz
- 250MHz
- 100.00MHz
- 250MHz
- All blocking capacitors to be placed near DSP
  to keep connecting routes short and minimize vias
- PCI CLOCK MUX
- (LVDS)
- (HCSL)
- SEL
- I/p PAIR SEL
- LOW
- IN2/IN2#
- HIGH
- IN1/IN1#
- SMART REFLEX
- DIR = 0 --> B to A
  DIR = 1 --> A to B
- Reserved for future use
  Not supported at this time
